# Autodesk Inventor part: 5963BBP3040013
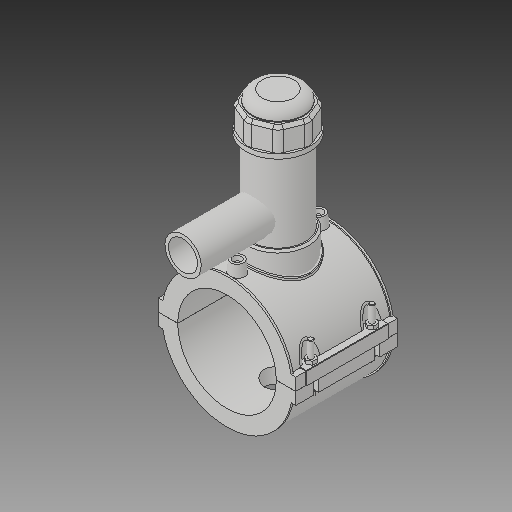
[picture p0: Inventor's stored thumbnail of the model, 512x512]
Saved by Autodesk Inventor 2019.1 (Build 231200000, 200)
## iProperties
Created: 2017-07
Part Number: 5963BBP3040013
Material: Generic
Description: PLASSON TAPPING SADDLE 4''IPS x 1 1/4''IPS
Document SubType Name: Modeling
Designer: KIM
Density: 1 g/cm^3
Appearance: Default
Author: KIM
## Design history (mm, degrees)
derived "5963BBP_5963BUP.ipt"
feature "Solid1::5963BBP_5963BUP.ipt"
feature "Solid2::5963BBP_5963BUP.ipt"
feature "Solid3::5963BBP_5963BUP.ipt"
tag "TaggingFeature1"
body "Solid1"
body "Solid2"
body "Solid3"
other parameters: "d0" = 114.1, "d2" = 159.004, "d3" = 28.525, "d4" = 118.11, "d5" = 0, "d6" = 0.1, "d8" = 0, "d19" = 6, "d20" = 6, "d21" = 70.866, "d23" = 0, "d24" = 35.433, "d26" = 0, "d27" = 3, "d28" = 3, "d29" = 3, "d30" = 38.03333, "d31" = 6, "d32" = 0, "d33" = 0, "d34" = 0.6, "d40" = 77.1316, "d41" = 74.165, "d43" = 0, "d45" = 0, "d47" = 145.031, "d70" = 15, "d72" = 0, "d73" = 6, "d75" = 5, "d76" = 0, "d77" = 5.705, "d78" = 87.05, "d79" = 15, "d80" = 47.244, "d82" = 5 deg, "d84" = 4, "d85" = 14, "d86" = 0, "d87" = 3, "d88" = 0, "d89" = 1, "d90" = 1, "d91" = 94.488, "d92" = 0, "d93" = 0.5, "d94" = 60.05263, "d96" = 151.2966, "d97" = 2.3622, "d98" = 0, "d102" = 1.141, "d120" = 140 deg, "d121" = 24.228, "d122" = 20 deg, "d123" = 296.66, "d124" = 88.998, "d126" = 0, "d143" = 117.523, "d145" = 26.33077, "d149" = 1.7115, "d150" = 28.96385, "d153" = 118.11, "d154" = 0, "d156" = 74.165, "d157" = 160 deg, "d159" = 6.846, "d161" = 1.7115, "d162" = 70.866, "d163" = 0, "d164" = 57.05, "d167" = 11.41, "d168" = 72.3561, "d170" = 3.2805, "d172" = 0, "d173" = 1, "d175" = 57.05, "d176" = 20 deg, "d177" = 7.987, "d178" = 34.23, "d180" = 0, "d183" = 13.692, "d184" = 6.3896, "d185" = 38.38575, "d186" = 38.38575, "d187" = 74.165, "d188" = 10.269, "d189" = 7.987, "d190" = 0, "d191" = 111.2475, "d193" = 6.9984, "d194" = 4.13385, "d195" = 90 deg, "d197" = 0, "d199" = 0, "d200" = 17.115, "d202" = 0, "d203" = 177.038, "d204" = 70.45675, "d205" = 51.9155, "d206" = 63.04025, "d207" = 132.7785, "d208" = 138.08964, "d209" = 164.64534, "d210" = 63.7819, "d211" = 74.165, "d212" = 59.332, "d213" = 39.5766, "d216" = 0, "d217" = 11.41, "d218" = 11.41, "d219" = 2.282, "d222" = 114.1, "d224" = 0, "d225" = 65.024, "d226" = 42.1, "d227" = 33.68, "d228" = 109.982, "d230" = 3.423, "d_" = 114.1, "B_" = 159.004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
